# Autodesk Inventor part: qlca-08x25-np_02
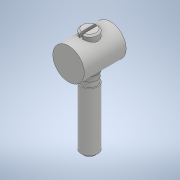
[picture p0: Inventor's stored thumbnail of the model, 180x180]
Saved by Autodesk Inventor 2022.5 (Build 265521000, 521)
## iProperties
Part Number: qlca-08x25-np_02
Material: 一般
Document SubType Name: Modeling
Designer: ImaoCorp
Density: 1 g/cm^3
Appearance: 既定
Author: ImaoCorp
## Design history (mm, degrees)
feature "qlca-08x25-np_02"
node "ソリッド1"
